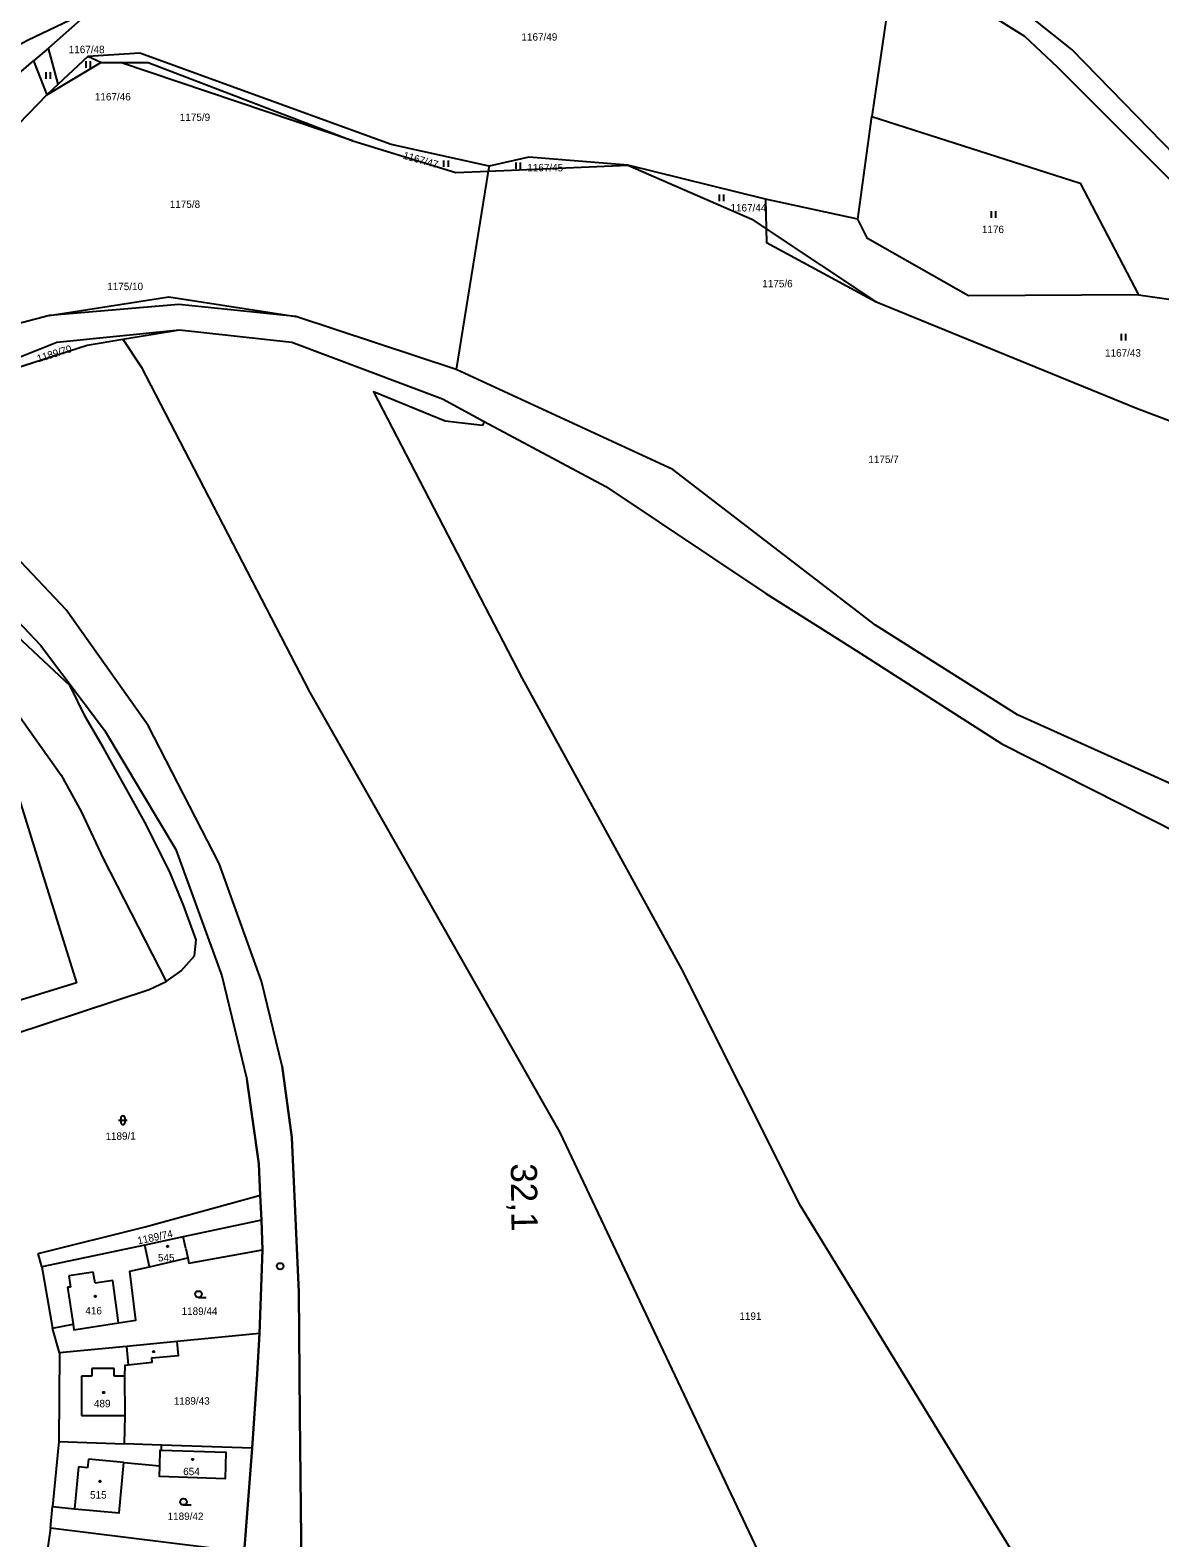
# Model space of a CAD drawing. Extents: x -793666 to -785424, y -1118958 to -1108761.
# Drawn here: x -787757.1 to -787498.3, y -1116599.4 to -1116254.2 of the extents above; entities that cross this region are included whole.
import ezdxf

# ---------------------------------------------------------------- set-up
doc = ezdxf.new("R2010")
doc.units = 0
for name, color, linetype in [('1', 7, 'Continuous'), ('Hranice parcel', 7, 'Continuous'), ('Parcelní čísla', 7, 'Continuous'), ('Vnitřní kresba', 7, 'Continuous'), ('Vrstva 55', 7, 'Continuous'), ('Vrstva 7', 7, 'Continuous'), ('Značky budov', 7, 'Continuous'), ('Značky kultur', 7, 'Continuous')]:
    doc.layers.add(name, color=color, linetype=linetype)

msp = doc.modelspace()

# ---------------------------------------------------------------- linework, layer by layer
at = {"layer": '1'}
msp.add_circle((-787699.82, -1116537.22), 0.75, dxfattribs=at)
at = {"layer": 'Hranice parcel'}
for p, q in [((-787559.79, -1116243.37), (-787564.29, -1116273.91)), ((-787742.96, -1116249.55), (-787752.92, -1116258.26)), ((-787752.92, -1116258.26), (-787756.31, -1116261.22)), ((-787750.69, -1116266.52), (-787752.92, -1116258.26)), ((-787756.31, -1116261.22), (-787753.31, -1116268.95)), ((-787753.31, -1116268.95), (-787740.89, -1116261.54)), ((-787743.85, -1116260.18), (-787750.69, -1116266.52)), ((-787740.89, -1116261.54), (-787743.85, -1116260.18)), ((-787740.89, -1116261.54), (-787736.41, -1116261.56)), ((-787683.18, -1116279.52), (-787736.41, -1116261.56)), ((-787750.69, -1116266.52), (-787753.31, -1116268.95)), ((-787567.47, -1116297.42), (-787564.29, -1116273.91)), ((-787652.15, -1116286.45), (-787620.19, -1116285.11)), ((-787651.97, -1116285.32), (-787652.15, -1116286.45)), ((-787588.65, -1116292.87), (-787620.19, -1116285.11)), ((-787652.15, -1116286.45), (-787659.49, -1116331.88)), ((-787567.47, -1116297.42), (-787588.65, -1116292.87)), ((-787588.65, -1116292.87), (-787588.47, -1116299.65)), ((-787588.47, -1116299.65), (-787563.43, -1116316.28)), ((-787752.64, -1116319.5), (-787800.27, -1116331.85)), ((-787659.49, -1116331.88), (-787696.23, -1116319.73)), ((-787735.88, -1116324.94), (-787722.89, -1116322.78)), ((-787744.01, -1116326.3), (-787735.88, -1116324.94)), ((-787735.88, -1116324.94), (-787731.65, -1116331.28)), ((-787653.08, -1116343.75), (-787653.49, -1116344.69)), ((-787705.48, -1116521.22), (-787704.38, -1116520.92)), ((-787704.38, -1116520.92), (-787704.1, -1116526.68)), ((-787704.1, -1116526.68), (-787703.91, -1116533.48)), ((-787754.45, -1116537.36), (-787755.27, -1116534.26)), ((-787730.84, -1116532.35), (-787754.45, -1116537.36)), ((-787729.78, -1116537.32), (-787730.84, -1116532.35)), ((-787703.91, -1116533.48), (-787704.56, -1116552.61)), ((-787754.45, -1116537.36), (-787751.94, -1116551.42)), ((-787750.4, -1116557.03), (-787751.94, -1116551.42)), ((-787704.56, -1116552.61), (-787723.43, -1116554.43)), ((-787750.4, -1116557.03), (-787750.49, -1116577.34)), ((-787750.49, -1116577.34), (-787751.96, -1116592.22)), ((-787750.49, -1116577.34), (-787735.49, -1116577.85)), ((-787726.99, -1116578.15), (-787735.49, -1116577.85)), ((-787727.03, -1116579.29), (-787726.99, -1116578.15)), ((-787706.23, -1116578.86), (-787726.99, -1116578.15)), ((-787706.23, -1116578.86), (-787708.05, -1116602.7)), ((-787752.45, -1116597.2), (-787751.96, -1116592.22)), ((-787752.45, -1116597.2), (-787755.32, -1116616.93)), ((-787708.05, -1116602.7), (-787752.45, -1116597.2))]:
    msp.add_line(p, q, dxfattribs=at)
for points in [[(-787559.79, -1116243.37), (-787548.03, -1116246.08), (-787536.05, -1116251.32), (-787529.36, -1116255.54), (-787521.82, -1116262.58), (-787446.99, -1116337.41), (-787434.65, -1116347.85), (-787426.61, -1116352.34), (-787368.83, -1116378.44), (-787186.27, -1116460.48)], [(-787353.58, -1116279.74), (-787370.99, -1116373.22), (-787424.94, -1116349.06), (-787432.69, -1116344.75), (-787444.35, -1116334.63), (-787518.47, -1116258.57), (-787527.13, -1116251.76), (-787534.26, -1116247.37)], [(-787742.96, -1116249.55), (-787757.71, -1116256.57), (-787773.26, -1116265.02), (-787791.8, -1116281.83), (-787826.54, -1116317.41)], [(-787764.47, -1116266.63), (-787762.28, -1116264.82), (-787761.33, -1116265.55), (-787756.31, -1116261.22)], [(-787651.97, -1116285.32), (-787674.4, -1116280.34), (-787732, -1116259.41), (-787743.85, -1116260.18)], [(-787736.41, -1116261.56), (-787730.04, -1116261.58), (-787683.18, -1116279.52)], [(-787753.31, -1116268.95), (-787781.38, -1116297.98), (-787800.27, -1116331.85)], [(-787564.29, -1116273.91), (-787516.57, -1116289.2), (-787503.22, -1116314.79)], [(-787683.18, -1116279.52), (-787659.58, -1116286.76), (-787652.15, -1116286.45)], [(-787620.19, -1116285.11), (-787642.83, -1116283.25), (-787651.97, -1116285.32)], [(-787620.19, -1116285.11), (-787591.82, -1116297.43), (-787588.47, -1116299.65)], [(-787588.47, -1116299.65), (-787588.39, -1116302.83), (-787563.43, -1116316.28)], [(-787503.22, -1116314.79), (-787542.14, -1116315.03), (-787565.32, -1116301.89), (-787567.47, -1116297.42)], [(-787752.64, -1116319.5), (-787725.3, -1116315.25), (-787696.23, -1116319.73)], [(-787563.43, -1116316.28), (-787503.71, -1116340.69), (-787452.07, -1116360.22)], [(-787503.22, -1116314.79), (-787475.36, -1116318.76), (-787444.55, -1116345.15)], [(-787696.23, -1116319.73), (-787723.04, -1116317.02), (-787752.64, -1116319.5)], [(-787796.66, -1116346.09), (-787775.84, -1116335.51), (-787751, -1116325.62), (-787722.89, -1116322.78)], [(-787722.89, -1116322.78), (-787697.16, -1116325.6), (-787662.68, -1116338.61), (-787653.08, -1116343.75)], [(-787796.66, -1116346.09), (-787764.77, -1116332.97), (-787744.01, -1116326.3)], [(-787731.65, -1116331.28), (-787693.03, -1116405.8), (-787635.8, -1116506.59), (-787568.9, -1116647.88)], [(-787488.04, -1116430.26), (-787530.91, -1116410.97), (-787563.47, -1116390.39), (-787609.91, -1116354.75), (-787659.49, -1116331.88)], [(-787653.49, -1116344.69), (-787662.05, -1116343.67), (-787678.42, -1116337), (-787644.49, -1116402.5), (-787607.93, -1116469.17), (-787580.95, -1116522.92), (-787526.69, -1116611.5)], [(-787653.08, -1116343.75), (-787625.26, -1116358.63), (-787588.56, -1116383.15), (-787567.91, -1116396.19), (-787534.55, -1116417.55), (-787480.18, -1116445.03), (-787453.34, -1116453.59), (-787373.09, -1116475.73), (-787293.48, -1116503.44), (-787218.24, -1116534.34)], [(-787693.98, -1116663.52), (-787691.68, -1116661.08), (-787693.44, -1116656.57), (-787695.13, -1116646.88), (-787694.77, -1116620.61), (-787695.36, -1116571.42), (-787695.53, -1116543.16), (-787697.17, -1116507.73), (-787699.35, -1116491.37), (-787704.1, -1116471.95), (-787713.77, -1116444.97), (-787730.07, -1116413.4), (-787748.85, -1116386.9), (-787769.63, -1116365.02), (-787796.66, -1116346.09)], [(-787809.33, -1116349.7), (-787801.57, -1116354.26), (-787773.08, -1116375.71), (-787754.69, -1116394.98), (-787740.05, -1116414.46), (-787723.7, -1116441.75), (-787713.22, -1116470.7), (-787707.44, -1116494.38), (-787704.74, -1116513.73), (-787704.38, -1116520.92)], [(-787725.95, -1116472.01), (-787722.51, -1116469.58), (-787719.42, -1116466.14), (-787719.06, -1116462.43), (-787721.94, -1116454.54), (-787725.06, -1116447.09), (-787730.48, -1116436.2), (-787740.3, -1116418.54), (-787744.48, -1116411.34), (-787747.91, -1116404.33), (-787760.07, -1116392.95), (-787768.48, -1116384.12), (-787783.23, -1116370.57), (-787789.77, -1116365.68), (-787796.38, -1116361.2), (-787803.06, -1116357.15), (-787810.31, -1116354.2), (-787814.88, -1116352.94)], [(-787848.15, -1116369.53), (-787838.93, -1116367), (-787816.95, -1116360.96), (-787783.07, -1116383.09), (-787773.29, -1116393.47), (-787764.99, -1116403.74), (-787750.02, -1116424.78), (-787745.39, -1116433.08), (-787740.36, -1116443.85), (-787725.95, -1116472.01)], [(-787783.74, -1116474.49), (-787804.46, -1116408.04), (-787786.89, -1116402.68), (-787778, -1116431.3), (-787772.45, -1116429.58), (-787760.88, -1116425.98), (-787755.47, -1116443.43), (-787746.51, -1116472.35), (-787781.13, -1116482.98)], [(-787776.83, -1116489.36), (-787729.82, -1116473.87), (-787725.95, -1116472.01)], [(-787755.27, -1116534.26), (-787730.74, -1116528.21), (-787705.48, -1116521.22)], [(-787704.1, -1116526.68), (-787722.02, -1116530.48), (-787730.84, -1116532.35)], [(-787729.78, -1116537.32), (-787721.01, -1116535.26), (-787720.75, -1116536.47), (-787703.91, -1116533.48)], [(-787751.94, -1116551.42), (-787747.28, -1116550.47), (-787747.09, -1116551.78), (-787736.85, -1116550.2), (-787732.87, -1116549.58), (-787734.24, -1116538.36), (-787729.78, -1116537.32)], [(-787723.43, -1116554.43), (-787735.01, -1116555.55), (-787750.4, -1116557.03)], [(-787735.49, -1116577.85), (-787735.33, -1116571.39), (-787735.39, -1116562.39), (-787735.34, -1116559.83), (-787734.61, -1116559.75), (-787729.11, -1116559.14), (-787729.2, -1116558.2), (-787723.12, -1116557.61), (-787723.43, -1116554.43)], [(-787704.56, -1116552.61), (-787705.09, -1116561.9), (-787706.23, -1116578.86)], [(-787727.03, -1116579.29), (-787712.3, -1116579.8), (-787712.46, -1116585.85), (-787727.48, -1116585.32), (-787727.4, -1116582.93)], [(-787727.4, -1116582.93), (-787727.28, -1116579.29), (-787727.03, -1116579.29)], [(-787751.96, -1116592.22), (-787746.92, -1116592.74), (-787736.74, -1116593.67), (-787735.66, -1116582.13), (-787727.4, -1116582.93)]]:
    msp.add_lwpolyline(points, dxfattribs=at)
at = {"layer": 'Vnitřní kresba'}
for p, q in [((-787721.46, -1116533.12), (-787722.02, -1116530.48)), ((-787721.46, -1116533.12), (-787721.01, -1116535.26)), ((-787742.63, -1116538.57), (-787748.25, -1116539.4)), ((-787748.25, -1116539.4), (-787747.86, -1116541.97)), ((-787742.21, -1116541.11), (-787742.63, -1116538.57)), ((-787738.19, -1116540.51), (-787742.21, -1116541.11)), ((-787736.85, -1116550.2), (-787738.19, -1116540.51)), ((-787747.86, -1116541.97), (-787748.53, -1116542.01)), ((-787748.53, -1116542.01), (-787747.28, -1116550.47)), ((-787735.01, -1116555.55), (-787734.61, -1116559.75)), ((-787742.94, -1116560.59), (-787742.96, -1116562.36)), ((-787737.86, -1116560.66), (-787742.94, -1116560.59)), ((-787737.88, -1116562.37), (-787737.86, -1116560.66)), ((-787742.96, -1116562.36), (-787745.35, -1116562.41)), ((-787745.35, -1116562.41), (-787745.35, -1116571.36)), ((-787735.39, -1116562.39), (-787737.88, -1116562.37)), ((-787745.35, -1116571.36), (-787735.33, -1116571.39)), ((-787743.75, -1116581.41), (-787743.93, -1116583.35)), ((-787735.66, -1116582.13), (-787743.75, -1116581.41)), ((-787746.02, -1116583.14), (-787746.92, -1116592.74)), ((-787743.93, -1116583.35), (-787746.02, -1116583.14))]:
    msp.add_line(p, q, dxfattribs=at)
at = {"layer": 'Vrstva 55'}
for points in [[(-787699.35, -1116491.37), (-787697.17, -1116507.73), (-787695.53, -1116543.16), (-787695.36, -1116571.42), (-787694.77, -1116620.61), (-787695.13, -1116646.88), (-787693.44, -1116656.57), (-787691.68, -1116661.08), (-787693.98, -1116663.52), (-787694.14, -1116669.51), (-787694.47, -1116681.92), (-787692.19, -1116731.59), (-787692.06, -1116734.36), (-787686.63, -1116766.25), (-787678.51, -1116793.87), (-787663.57, -1116829.76), (-787646.12, -1116860.74), (-787626.1, -1116888.93), (-787601.65, -1116916.45), (-787576.19, -1116941.14), (-787514.87, -1116995.01), (-787496.65, -1117010.38), (-787458.26, -1117042.74)], [(-787708.05, -1116602.7), (-787706.23, -1116578.86), (-787705.09, -1116561.9), (-787704.56, -1116552.61), (-787703.91, -1116533.48), (-787704.1, -1116526.68), (-787704.38, -1116520.92), (-787704.74, -1116513.73), (-787707.44, -1116494.38)]]:
    msp.add_lwpolyline(points, dxfattribs=at)
at = {"layer": 'Značky budov'}
for centre in [(-787725.59, -1116532.63), (-787742.19, -1116544.12), (-787728.8, -1116556.74), (-787740.27, -1116566.11), (-787719.87, -1116581.45), (-787741.1, -1116586.44)]:
    msp.add_circle(centre, 0.175, dxfattribs=at)
at = {"layer": 'Značky kultur'}
for p, q in [((-787744.25, -1116262.77), (-787744.25, -1116261.27)), ((-787743.25, -1116262.77), (-787743.25, -1116261.27)), ((-787753.46, -1116265.31), (-787753.46, -1116263.81)), ((-787752.46, -1116265.31), (-787752.46, -1116263.81)), ((-787662.3, -1116285.49), (-787662.3, -1116283.99)), ((-787661.3, -1116285.49), (-787661.3, -1116283.99)), ((-787645.75, -1116285.96), (-787645.75, -1116284.46)), ((-787644.75, -1116285.96), (-787644.75, -1116284.46)), ((-787599.2, -1116293.33), (-787599.2, -1116291.83)), ((-787598.2, -1116293.33), (-787598.2, -1116291.83)), ((-787536.87, -1116297.11), (-787536.87, -1116295.61)), ((-787535.87, -1116297.11), (-787535.87, -1116295.61)), ((-787507.13, -1116325.23), (-787507.13, -1116323.73)), ((-787506.13, -1116325.23), (-787506.13, -1116323.73)), ((-787736.34, -1116503.28), (-787736.34, -1116504.28)), ((-787735.34, -1116504.28), (-787735.34, -1116503.28)), ((-787736.84, -1116503.78), (-787734.84, -1116503.78)), ((-787718.55, -1116544.38), (-787716.8, -1116544.38)), ((-787721.98, -1116591.87), (-787720.23, -1116591.87))]:
    msp.add_line(p, q, dxfattribs=at)
for centre in [(-787718.55, -1116543.63), (-787721.98, -1116591.12)]:
    msp.add_circle(centre, 0.75, dxfattribs=at)
for centre, start, end in [((-787735.84, -1116503.28), 0, 180), ((-787735.84, -1116504.28), 180, 359.9879)]:
    msp.add_arc(centre, 0.5, start, end, dxfattribs=at)

# ---------------------------------------------------------------- texts
at = {"layer": 'Parcelní čísla'}
for s, p in [('1167/49', (-787644.56, -1116256.57)), ('1167/48', (-787748.26, -1116259.44)), ('1167/46', (-787742.27, -1116270.27)), ('1175/9', (-787722.82, -1116274.96)), ('1167/45', (-787643.22, -1116286.5)), ('1175/8', (-787725.12, -1116294.88)), ('1167/44', (-787596.68, -1116295.69)), ('1176', (-787539.09, -1116300.64)), ('1175/10', (-787739.44, -1116313.7)), ('1175/6', (-787589.39, -1116313.05)), ('1167/43', (-787510.88, -1116328.92)), ('1175/7', (-787565.1, -1116353.29)), ('545', (-787727.82, -1116536.1)), ('416', (-787744.45, -1116548.24)), ('1189/44', (-787722.41, -1116548.35)), ('1191', (-787594.63, -1116549.48)), ('489', (-787742.48, -1116569.5)), ('1189/43', (-787724.19, -1116568.9)), ('654', (-787722.04, -1116585.05)), ('515', (-787743.37, -1116590.41)), ('1189/42', (-787725.61, -1116595.31))]:
    msp.add_text(s, height=1.7, dxfattribs=at).set_placement(p)
for s, rotation, p in [('1167/47', 344, (-787671.81, -1116283.57)), ('1189/70', 17, (-787755.25, -1116330.24)), ('1189/1', 1, (-787739.84, -1116508.31)), ('1189/74', 12, (-787732.33, -1116532.22))]:
    msp.add_text(s, height=1.7, rotation=rotation, dxfattribs=at).set_placement(p)
at = {"layer": 'Vrstva 7'}
msp.add_text('32,1', height=6, rotation=270.7126, dxfattribs=at).set_placement((-787647.01, -1116513.66))

doc.saveas('drawing.dxf')
